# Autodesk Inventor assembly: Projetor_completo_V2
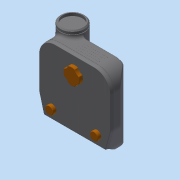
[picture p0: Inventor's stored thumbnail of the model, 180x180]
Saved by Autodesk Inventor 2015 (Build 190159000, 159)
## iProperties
Created: 2015-05
Part Number: Projetor_completo_V2
Document SubType Name: Assembly
Designer: TREINA8
Author: TREINA8
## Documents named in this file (4)
- C:\Users\TREINA8\Desktop\Prototype\Projetor_completo_V2.iam
- C:\Users\TREINA8\Desktop\Prototype\Projector_V2.ipt
- C:\Users\TREINA8\Desktop\Prototype\BOTOES.ipt
- C:\Users\TREINA8\Desktop\Prototype\BOTOES_SUPORTE.ipt
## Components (3 placed, 3 different names)
1. Projector_V2:1 — Flush:1, Flush:2, Flush:3
2. BOTOES:1 — Flush:1, Flush:2
3. BOTOES_SUPORTE:1 — Flush:3
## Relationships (3: Flush 3)
- Flush:1: Projector_V2:1 ↔ BOTOES:1
- Flush:2: Projector_V2:1 ↔ BOTOES:1
- Flush:3: Projector_V2:1 ↔ BOTOES_SUPORTE:1
